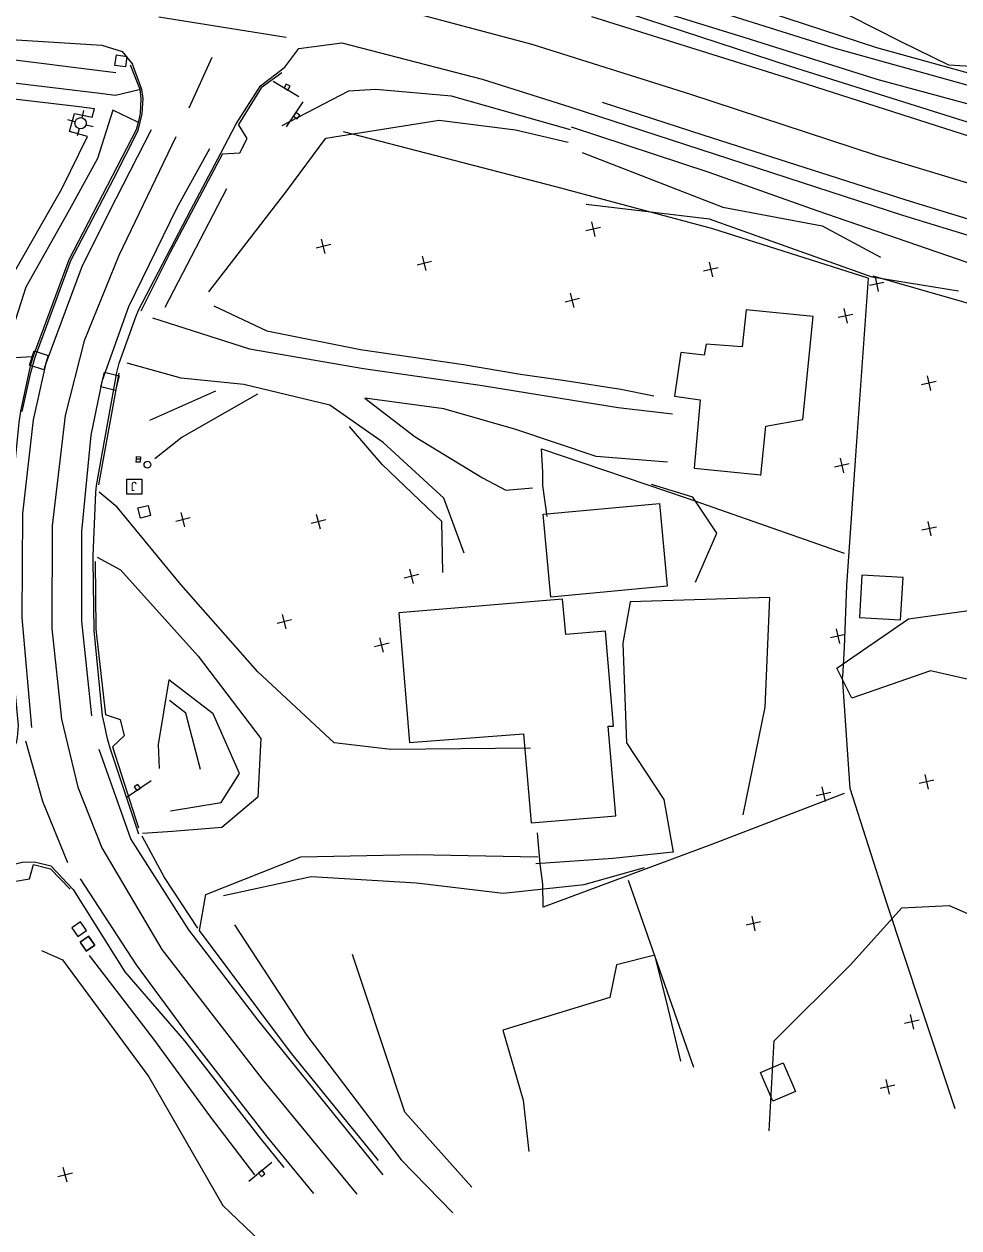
# Model space of a CAD drawing. Extents: x 4711259 to 4716401, y 890074 to 892728.
# Drawn here: x 4714778.1 to 4715089.6, y 890917.4 to 891318.6 of the extents above; entities that cross this region are included whole.
import ezdxf

# ---------------------------------------------------------------- set-up
doc = ezdxf.new("R2010")
doc.units = 0
for name, color, linetype in [('E_HY_STORM_Inlet', 7, 'Continuous'), ('E_LDSC_PHOTOG_Treeline', 7, 'Continuous'), ('E_RDWY_PHOTOG_Eave', 7, 'Continuous'), ('E_RDWY_PHOTOG_Fence', 7, 'Continuous'), ('E_RDWY_ROAD_Bikeway', 7, 'Continuous'), ('E_RDWY_ROAD_Curb', 7, 'Continuous'), ('E_RDWY_ROAD_EdgeAsph', 7, 'Continuous'), ('E_RDWY_ROAD_EdgeGravel', 7, 'Continuous'), ('E_RDWY_ROAD_Mailbox', 7, 'Continuous'), ('E_RDWY_ROAD_Sidewalk', 7, 'Continuous'), ('E_RDWY_ROAD_Striping', 7, 'Continuous'), ('E_RDWY_ROAD_TBofCurb', 7, 'Continuous'), ('E_TERR_DTM_BrkLines', 7, 'Continuous'), ('E_TERR_DTM_RandomPt', 7, 'Continuous'), ('E_TRAF_SIGN_PrivateSign', 7, 'Continuous'), ('E_TRAF_SIGN_PublicSign', 7, 'Continuous'), ('E_UTIL_COMM_General', 7, 'Continuous'), ('E_UTIL_ELEC_GENERAL', 7, 'Continuous'), ('E_UTIL_MISC_General', 7, 'Continuous'), ('E_UTIL_WTR_General', 7, 'Continuous')]:
    doc.layers.add(name, color=color, linetype=linetype)

msp = doc.modelspace()

# ---------------------------------------------------------------- linework, layer by layer
at = {"layer": 'E_HY_STORM_Inlet'}
for p, q in [((4714783.08, 891206.57), (4714783.08, 891206.57)), ((4714806.74, 891199.57), (4714806.74, 891199.57))]:
    msp.add_line(p, q, dxfattribs=at)
for points in [[(4714784.71, 891203.44), (4714779.95, 891204.94), (4714781.46, 891209.71), (4714786.22, 891208.2)], [(4714804.92, 891202.6), (4714809.77, 891201.38), (4714808.55, 891196.53), (4714803.7, 891197.75)]]:
    msp.add_lwpolyline(points, close=True, dxfattribs=at)
at = {"layer": 'E_LDSC_PHOTOG_Treeline'}
msp.add_lwpolyline([(4715107.9, 891096.71), (4715080.13, 891103.04), (4715053.95, 891093.97), (4715048.94, 891104), (4715072.76, 891120.43), (4715099.29, 891124.02), (4715112.14, 891115.47), (4715111.67, 891101.74)], dxfattribs=at)
at = {"layer": 'E_RDWY_PHOTOG_Eave'}
for points in [[(4715023.61, 891168.22), (4715025.23, 891184.62), (4715037.57, 891186.84), (4715040.98, 891221.12), (4715018.75, 891223.4), (4715017.35, 891211.08), (4715005.34, 891211.95), (4715004.68, 891208.27), (4714996.95, 891209.14), (4714994.86, 891194.66), (4715003.4, 891193.37), (4715001.35, 891170.57), (4715023.59, 891168.44)], [(4714906.49, 891079.18), (4714944.48, 891082.13), (4714947.08, 891052.41), (4714975.32, 891054.7), (4714972.73, 891084.6), (4714974.53, 891084.66), (4714971.82, 891116.26), (4714958.66, 891115.16), (4714957.47, 891126.94), (4714903.03, 891122.43), (4714906.5, 891079.08)]]:
    msp.add_lwpolyline(points, dxfattribs=at)
for points in [[(4714992.4, 891131.25), (4714953.62, 891127.68), (4714951.08, 891155.33), (4714989.85, 891158.9)], [(4715070.98, 891134.17), (4715057.25, 891134.96), (4715056.44, 891120.87), (4715070.17, 891120.08)], [(4715031.05, 890972.41), (4715035.15, 890962.91), (4715027.65, 890959.67), (4715023.54, 890969.17)]]:
    msp.add_lwpolyline(points, close=True, dxfattribs=at)
at = {"layer": 'E_RDWY_PHOTOG_Fence'}
for points in [[(4714955.27, 891264.38), (4714884.56, 891282.73)], [(4715059.4, 891233.98), (4715007.66, 891250.39), (4714955.27, 891264.38)], [(4715059.4, 891233.98), (4715055.24, 891176.4), (4715052.19, 891131.51), (4715051.31, 891110.84), (4715050.8, 891101.12)], [(4715186.39, 891197.91), (4715122.24, 891217.01), (4715061.03, 891234.6)], [(4714952.41, 891154.5), (4714950.96, 891164.8), (4714950.92, 891169.25), (4714950.57, 891177.09), (4714999.06, 891160.57), (4715051.34, 891142.26)], [(4715088.29, 890957.1), (4715077.12, 890990.71), (4715065.62, 891025.64), (4715053.37, 891063.81), (4715050.8, 891101.12)], [(4715051.31, 891062.18), (4715007.5, 891045.35), (4714951.11, 891024.27), (4714950.93, 891031.93), (4714950.11, 891038.8), (4714949.19, 891049.09)], [(4714979.38, 891033.35), (4715001.14, 890970.95)]]:
    msp.add_lwpolyline(points, dxfattribs=at)
at = {"layer": 'E_RDWY_ROAD_Bikeway'}
msp.add_lwpolyline([(4714960.53, 891338.2), (4714992.07, 891328.41), (4715047.87, 891310.67), (4715104.55, 891294.88), (4715161.82, 891279.58), (4715217.87, 891264.44), (4715268.34, 891251.28), (4715285.12, 891247.96), (4715289.15, 891255.65), (4715287.17, 891288.16), (4715277.94, 891331.31), (4715273.98, 891372.25)], dxfattribs=at)
at = {"layer": 'E_RDWY_ROAD_Curb'}
for points in [[(4714777.56, 891189.52), (4714780.34, 891202.47), (4714781.84, 891207.67), (4714793.67, 891239.87), (4714808, 891267.2), (4714816.14, 891283.15), (4714817.46, 891288.67), (4714817.8, 891293.79), (4714817.39, 891296.78), (4714814.29, 891305.29)], [(4714794.5, 891030.18), (4714787.19, 891037.94), (4714781.47, 891039.34), (4714777.5, 891039.18), (4714773.52, 891038.19), (4714769.87, 891037.1), (4714745.06, 891031.26), (4714715.63, 891028.71), (4714712.38, 891028.49), (4714697.92, 891027.61), (4714694.04, 891027.64), (4714666.46, 891026.17), (4714621.96, 891023.85), (4714619.54, 891023.9), (4714581.88, 891021.84), (4714537.04, 891019.62), (4714477.81, 891016.45)]]:
    msp.add_lwpolyline(points, dxfattribs=at)
at = {"layer": 'E_RDWY_ROAD_EdgeAsph'}
for points in [[(4715274.37, 891239.3), (4715279.91, 891242.26), (4715243.55, 891251.46), (4715202.85, 891263.05), (4715152.49, 891276.57), (4715108.79, 891287.62), (4715062.32, 891300.11), (4715019.77, 891313.64), (4714960.1, 891332.16)], [(4715104.58, 891282.25), (4715091.02, 891286.36), (4715033.48, 891304.49), (4714973.76, 891324.04), (4714960.29, 891328.61)], [(4714412.07, 891317.13), (4714421.12, 891318.22), (4714480.4, 891321.25), (4714536.91, 891324.63), (4714588.2, 891323.89), (4714641.59, 891321.38), (4714698.61, 891318.18), (4714754.2, 891314.67), (4714804.09, 891311.59), (4714810.85, 891309.49), (4714814.29, 891305.29)], [(4714865.02, 891304.31), (4714869.63, 891310.48), (4714883.99, 891312.35), (4714930.79, 891300.25), (4714959.91, 891291.07)], [(4714816.41, 891048.61), (4714806.85, 891077.27), (4714805.98, 891080.42), (4714804.92, 891085.14), (4714804.29, 891088.1), (4714801.49, 891116.55), (4714801.14, 891139.96), (4714801.17, 891141.55), (4714802.01, 891162.53), (4714802.27, 891164.88), (4714809.05, 891202.48), (4714809.84, 891205.61), (4714815.37, 891221.06), (4714816.31, 891223.24), (4714833.7, 891256.67), (4714843.66, 891275.57), (4714845.08, 891278.21), (4714847.52, 891282.87), (4714848.84, 891285.37), (4714856.94, 891298.05), (4714865.02, 891304.31)], [(4714959.91, 891291.07), (4715070.78, 891254.96), (4715096.24, 891247.13)], [(4714946.85, 891077.32), (4714900.38, 891076.82), (4714881.4, 891079.06), (4714856.02, 891102.71), (4714830.42, 891131.89), (4714809.11, 891157.66), (4714803.21, 891162.67)], [(4714802.51, 891140.94), (4714810.22, 891136.71), (4714836.16, 891107.98), (4714856.99, 891080.53), (4714856.07, 891061.02), (4714844.04, 891050.81), (4714827.56, 891049.54), (4714817.64, 891048.85)], [(4714896.24, 890939.9), (4714866.93, 890975.97), (4714836.57, 891016.5), (4714838.65, 891028.5), (4714870.33, 891041.1), (4714908.8, 891041.84), (4714949.25, 891041.14)], [(4714794.5, 891030.18), (4714811.75, 891002.79), (4714831.64, 890979.81), (4714856.81, 890947.31), (4714864.71, 890937.51)]]:
    msp.add_lwpolyline(points, dxfattribs=at)
at = {"layer": 'E_RDWY_ROAD_EdgeGravel'}
for points in [[(4715129.83, 891296.82), (4715131.22, 891300.37), (4715148.01, 891299.58), (4715169.77, 891296.66), (4715178.93, 891319.61), (4715159.28, 891322.41), (4715145.29, 891327.38), (4715136.27, 891339.29), (4715135.98, 891355.43), (4715142.7, 891381.21), (4715152.35, 891398.28), (4715174.07, 891425.28), (4715152.41, 891442.38), (4715131.25, 891448.73), (4715127.61, 891412.55), (4715124.8, 891383.92), (4715121.22, 891343.23), (4715118.2, 891317.27), (4715115.53, 891303.61), (4715110.39, 891299.56), (4715096.75, 891301.17), (4715062.25, 891310.71), (4715026.27, 891322.49), (4714993.7, 891330.91)], [(4714960.2, 891283.42), (4714920.51, 891294.62), (4714895.34, 891296.84), (4714886.25, 891296.23), (4714864.06, 891284.69)], [(4714960.4, 891284.34), (4715006.25, 891269.25), (4715042.29, 891256.46), (4715092.22, 891239.33), (4715128.79, 891228.29), (4715176.04, 891217.77), (4715229.02, 891205.03), (4715261.96, 891196.75), (4715272.04, 891183.8), (4715270.46, 891162.32), (4715267.8, 891132.71), (4715260.98, 891133.28)], [(4714845.57, 891263.7), (4714825.01, 891224.2)], [(4714820.98, 891220.75), (4714853.28, 891210.4), (4714891.25, 891203.84), (4714930.07, 891198.3), (4714976.11, 891190.86)], [(4714924.76, 891142.33), (4714917.96, 891160.57), (4714897.78, 891179.23), (4714880.03, 891191.59), (4714851.39, 891198.51), (4714830.49, 891200.67), (4714812.54, 891205.66)], [(4714992.46, 891172.66), (4714968.75, 891174.53), (4714942, 891183.48), (4714918, 891190.36), (4714891.72, 891193.98), (4714908.45, 891181.04), (4714930.91, 891167.4), (4714938.66, 891163.33), (4714947.5, 891164.06)], [(4714976.11, 891190.86), (4714994.19, 891188.73)], [(4714799.87, 891008.25), (4714821.3, 890980.32), (4714839.9, 890954.82), (4714854.95, 890935.06)], [(4714996.99, 890972.94), (4714992.22, 890993.02), (4714988.3, 891008.32), (4714975.54, 891005.12), (4714973.31, 890994.18), (4714937.59, 890983.32), (4714944.45, 890960.03), (4714946.31, 890942.91)]]:
    msp.add_lwpolyline(points, dxfattribs=at)
at = {"layer": 'E_RDWY_ROAD_Mailbox'}
for points in [[(4714798.97, 891016.57), (4714796.96, 891019.44), (4714794.09, 891017.43), (4714796.1, 891014.56)], [(4714801.67, 891011.77), (4714799.67, 891014.64), (4714796.8, 891012.63), (4714798.81, 891009.76)], [(4714801.67, 891011.66), (4714799.66, 891014.53), (4714796.8, 891012.52), (4714798.8, 891009.66)]]:
    msp.add_lwpolyline(points, close=True, dxfattribs=at)
at = {"layer": 'E_RDWY_ROAD_Sidewalk'}
for points in [[(4714816.5, 891296.69), (4714808.62, 891294.81), (4714802.45, 891295.59), (4714761.76, 891300.47)], [(4714759.61, 891295.53), (4714796.48, 891291.21), (4714801.58, 891290.53)], [(4714740.39, 891075.71), (4714762.07, 891076.89), (4714757.78, 891108.32), (4714757.55, 891143.53), (4714759.3, 891173.97), (4714761.75, 891192.58), (4714765.2, 891208.47), (4714758.18, 891210.11), (4714759.62, 891215.93), (4714767, 891214.2), (4714773.27, 891233.21), (4714790.74, 891263.77), (4714799.25, 891281.17), (4714793.25, 891282.77), (4714794.89, 891288.77), (4714800.82, 891287.57), (4714801.58, 891290.53)], [(4714816.03, 891285.88), (4714807.71, 891289.98), (4714802.61, 891273.83), (4714793.12, 891256.66), (4714778.72, 891230.97), (4714771.15, 891207.3), (4714780.69, 891207.86)], [(4714844.28, 891275.36), (4714850.06, 891275.66), (4714852.47, 891280.44), (4714849.57, 891285.19)], [(4714807.63, 891077.79), (4714811.61, 891081.53), (4714810.25, 891086.71), (4714805.32, 891088.38)], [(4714770.4, 891036.35), (4714774.68, 891032.83), (4714779.92, 891033.78), (4714781.25, 891038.5)]]:
    msp.add_lwpolyline(points, dxfattribs=at)
at = {"layer": 'E_RDWY_ROAD_Striping'}
for points in [[(4714888.76, 891327.56), (4714947.33, 891311.92)], [(4714967.14, 891321.14), (4715033.15, 891300.46), (4715090.68, 891282.05), (4715148, 891263.73), (4715202.12, 891249.54), (4715266.29, 891235.81)], [(4714947.33, 891311.92), (4715000.18, 891295.25), (4715061.97, 891274.93), (4715122.16, 891256.75), (4715178.28, 891241.22), (4715237.11, 891227.09), (4715270.84, 891220.22)], [(4714840.68, 891307.44), (4714833.04, 891290.62)], [(4715267.2, 891208.86), (4715234.23, 891215.79), (4715180.63, 891228.62), (4715123.12, 891244.3), (4715072.01, 891259.89), (4715004.43, 891281.64), (4714970.84, 891292.52)], [(4714780.77, 891084.16), (4714777.51, 891120.9), (4714777.75, 891155.5), (4714781.25, 891186.73), (4714785.5, 891205.56), (4714797.57, 891238.22), (4714808.77, 891260.52), (4714820.56, 891283.5)], [(4714828.68, 891281.1), (4714809.68, 891241.52), (4714798.18, 891213.11), (4714791.85, 891188.12), (4714787.48, 891151.35), (4714787.39, 891117.14), (4714790.61, 891086.99)], [(4714800.71, 891088.04), (4714797.34, 891119.61), (4714797.35, 891149.52), (4714800.49, 891181.6), (4714804.23, 891199.98), (4714813.01, 891224.55), (4714829.19, 891257.52), (4714840.04, 891277.19)], [(4714897.81, 890935.1), (4714856.04, 890986.77), (4714832.98, 891016.71), (4714813.74, 891047.11), (4714803.19, 891076.89)], [(4714804.01, 891044.05), (4714824.07, 891010.23), (4714857.48, 890967.03), (4714889.02, 890928.63)], [(4714874.69, 890928.88), (4714859.2, 890947.65), (4714832.98, 890981.42), (4714815.65, 891005.04), (4714796.93, 891033.8)]]:
    msp.add_lwpolyline(points, dxfattribs=at)
at = {"layer": 'E_RDWY_ROAD_TBofCurb'}
for points in [[(4714813.48, 891304.99), (4714816.67, 891296.91), (4714817.06, 891293.87), (4714816.78, 891288.8), (4714816.16, 891285.86), (4714815.48, 891283.33), (4714793.06, 891240.09), (4714781.17, 891207.95), (4714780.22, 891204.65), (4714776.92, 891189.64), (4714776.38, 891185.87), (4714773.42, 891155.74), (4714772.86, 891120.07), (4714776.18, 891084.87), (4714775.88, 891080.89), (4714775.48, 891079.03), (4714774.32, 891076.59), (4714769.02, 891071.22), (4714768.31, 891070.73), (4714764.77, 891068.82), (4714762.1, 891067.96)], [(4714864.03, 891302.4), (4714857.12, 891297.34), (4714849.57, 891285.19)], [(4714844.28, 891275.36), (4714826.87, 891242.7), (4714817.08, 891223)], [(4714809.67, 891202.23), (4714802.99, 891165.02)], [(4714801.85, 891139.47), (4714802.1, 891116.97), (4714805.32, 891088.38)], [(4714807.63, 891077.79), (4714816.31, 891050.76)], [(4714781.25, 891038.5), (4714786.94, 891037.11), (4714793.53, 891030.29)]]:
    msp.add_lwpolyline(points, dxfattribs=at)
at = {"layer": 'E_TERR_DTM_BrkLines'}
for points in [[(4715028.38, 891334.19), (4715070.04, 891312.89), (4715086.17, 891305.02), (4715103.25, 891304.05), (4715110.22, 891308.84), (4715118.68, 891335.69)], [(4714822.99, 891321.09), (4714865.48, 891314.24)], [(4714808.75, 891302.39), (4714767.9, 891307.46), (4714722.36, 891307.78), (4714714.06, 891307.54)], [(4714839.73, 891229.44), (4714865.66, 891263.03), (4714878.71, 891280.59), (4714916.43, 891286.57), (4714941.83, 891283.38), (4714959.42, 891279.22)], [(4714964.08, 891275.82), (4715010.94, 891257.66), (4715044.07, 891251.33), (4715063.52, 891240.94)], [(4715089.5, 891229.64), (4715060.7, 891234.33), (4715006.53, 891253.64), (4714965.42, 891258.52)], [(4714841.39, 891224.69), (4714859.01, 891216.42), (4714890.24, 891210.13), (4714924.58, 891205.19), (4714943.49, 891201.96), (4714958.39, 891199.79)], [(4714958.39, 891199.79), (4714977.01, 891196.91), (4714988, 891194.7)], [(4714841.94, 891196.3), (4714819.93, 891186.49)], [(4714855.89, 891195.29), (4714830.79, 891180.93), (4714821.66, 891173.7)], [(4714917.63, 891135.89), (4714917.36, 891152.83), (4714897.41, 891171.88), (4714886.53, 891184.54)], [(4715001.88, 891132.6), (4715008.9, 891148.95), (4715000.96, 891161), (4714987.18, 891165.17)], [(4715017.76, 891055.03), (4715024.99, 891090.99), (4715026.65, 891127.56), (4714980.02, 891126.03), (4714977.59, 891112.35), (4714978.86, 891079.11), (4714991.23, 891060.17), (4714994.44, 891042.64), (4714974.33, 891040.51), (4714948.66, 891038.72)], [(4714826.91, 891056.39), (4714843.77, 891059.2), (4714849.87, 891068.86), (4714841.15, 891088.7), (4714826.34, 891100.12), (4714822.79, 891078.56), (4714823.11, 891070.52)], [(4714836.92, 891070.16), (4714832.01, 891089), (4714826.58, 891093.2)], [(4714790.61, 891086.99), (4714796.05, 891064.33), (4714804.01, 891044.05)], [(4714778.59, 891079.73), (4714784.3, 891059.64), (4714792.58, 891039.19)], [(4714836.01, 891017.36), (4714824.95, 891034.23), (4714817.52, 891047.97)], [(4714844.57, 891028.22), (4714873.76, 891034.5), (4714908.86, 891032.44), (4714937.78, 891029.01), (4714964.71, 891031.91), (4714984.82, 891037.54)], [(4715026.42, 890949.72), (4715028.04, 890979.74), (4715053.31, 891005.02), (4715070.53, 891024.1), (4715086.38, 891024.84), (4715113.09, 891013.17), (4715126.01, 890996.89), (4715143.13, 890970.55), (4715149.96, 890957.06)], [(4714848.22, 891018.4), (4714872.31, 890981.54), (4714903.74, 890940.05), (4714921.04, 890922.39)], [(4714783.95, 891009.9), (4714790.89, 891006.8), (4714819.75, 890967.8), (4714844.39, 890924.9), (4714883.83, 890887.19), (4714907.11, 890866.26)], [(4714927.31, 890930.94), (4714904.95, 890955.98), (4714890.95, 890998.24), (4714887.58, 891008.53)]]:
    msp.add_lwpolyline(points, dxfattribs=at)
at = {"layer": 'E_TERR_DTM_RandomPt'}
for p, q in [((4714967.16, 891252.71), (4714968.25, 891247.83)), ((4714970.14, 891250.82), (4714965.26, 891249.73)), ((4714880.3, 891245.18), (4714875.46, 891243.93)), ((4714878.5, 891242.13), (4714877.25, 891246.97)), ((4714912.13, 891236.47), (4714910.88, 891241.31)), ((4714913.92, 891239.51), (4714909.08, 891238.26)), ((4715009.37, 891237.38), (4715004.49, 891236.29)), ((4715006.38, 891239.28), (4715007.47, 891234.4)), ((4715064.63, 891232.54), (4715059.75, 891231.45)), ((4715061.64, 891234.43), (4715062.73, 891229.55)), ((4714961.44, 891224.13), (4714960.19, 891228.97)), ((4714963.24, 891227.17), (4714958.4, 891225.92)), ((4715054.25, 891221.88), (4715049.37, 891220.79)), ((4715051.27, 891223.78), (4715052.36, 891218.9)), ((4715079.01, 891201.36), (4715080.1, 891196.48)), ((4715082, 891199.46), (4715077.12, 891198.37)), ((4715050.06, 891173.94), (4715051.15, 891169.06)), ((4715053.05, 891172.04), (4715048.17, 891170.95)), ((4714833.53, 891154.09), (4714828.69, 891152.84)), ((4714831.73, 891151.04), (4714830.48, 891155.88)), ((4714878.67, 891153.38), (4714873.83, 891152.13)), ((4714876.87, 891150.33), (4714875.62, 891155.17)), ((4715079.18, 891152.9), (4715080.27, 891148.02)), ((4715082.17, 891151.01), (4715077.29, 891149.92)), ((4714907.87, 891132.13), (4714906.62, 891136.97)), ((4714909.66, 891135.18), (4714904.82, 891133.93)), ((4714865.46, 891117.04), (4714864.21, 891121.88)), ((4714867.25, 891120.09), (4714862.41, 891118.83)), ((4715048.7, 891117.07), (4715049.79, 891112.19)), ((4714899.72, 891112.32), (4714894.88, 891111.07)), ((4714897.92, 891109.27), (4714896.67, 891114.11)), ((4715051.68, 891115.17), (4715046.8, 891114.08)), ((4715078.29, 891068.48), (4715079.38, 891063.6)), ((4715043.94, 891064.41), (4715045.03, 891059.53)), ((4715081.27, 891066.59), (4715076.39, 891065.5)), ((4715046.92, 891062.52), (4715042.04, 891061.43)), ((4715020.56, 891021.35), (4715021.65, 891016.47)), ((4715023.54, 891019.45), (4715018.66, 891018.36)), ((4715073.4, 890988.55), (4715074.49, 890983.67)), ((4715076.38, 890986.66), (4715071.5, 890985.57)), ((4715068.2, 890965.02), (4715063.32, 890963.93)), ((4715065.22, 890966.92), (4715066.31, 890962.04)), ((4714794.26, 890935.71), (4714789.42, 890934.46)), ((4714792.46, 890932.67), (4714791.21, 890937.51))]:
    msp.add_line(p, q, dxfattribs=at)
at = {"layer": 'E_TRAF_SIGN_PrivateSign'}
for p, q in [((4714865.52, 891284.35), (4714871.08, 891292.66)), ((4714868.92, 891288.09), (4714868.92, 891288.09))]:
    msp.add_line(p, q, dxfattribs=at)
msp.add_lwpolyline([(4714867.88, 891287.88), (4714869.13, 891287.05), (4714869.96, 891288.29), (4714868.72, 891289.13)], close=True, dxfattribs=at)
at = {"layer": 'E_TRAF_SIGN_PublicSign'}
for p, q in [((4714869.68, 891294.42), (4714861.09, 891299.54)), ((4714865.77, 891297.63), (4714865.77, 891297.63)), ((4714820.45, 891066.36), (4714812.15, 891060.79)), ((4714815.88, 891064.2), (4714815.88, 891064.2)), ((4714853.01, 890932.97), (4714860.73, 890939.32)), ((4714857.35, 890935.57), (4714857.35, 890935.57))]:
    msp.add_line(p, q, dxfattribs=at)
for points in [[(4714866.03, 891296.6), (4714866.8, 891297.89), (4714865.51, 891298.65), (4714864.74, 891297.37)], [(4714816.93, 891063.99), (4714816.09, 891065.24), (4714814.84, 891064.4), (4714815.68, 891063.16)], [(4714856.29, 890935.67), (4714857.24, 890934.51), (4714858.4, 890935.46), (4714857.45, 890936.62)]]:
    msp.add_lwpolyline(points, close=True, dxfattribs=at)
at = {"layer": 'E_UTIL_COMM_General'}
for points in [[(4714808.94, 891308.33), (4714812.4, 891307.82), (4714811.89, 891304.36), (4714808.42, 891304.87)], [(4714816.9, 891154), (4714816.07, 891157.4), (4714819.47, 891158.23), (4714820.3, 891154.83)]]:
    msp.add_lwpolyline(points, close=True, dxfattribs=at)
at = {"layer": 'E_UTIL_ELEC_GENERAL'}
msp.add_lwpolyline([(4714812.38, 891167.01), (4714817.38, 891166.97), (4714817.33, 891161.97), (4714812.33, 891162.01)], close=True, dxfattribs=at)
at = {"layer": 'E_UTIL_MISC_General'}
for points in [[(4714816.78, 891172.57), (4714815.49, 891172.64), (4714815.55, 891173.71), (4714816.84, 891173.64)], [(4714815.55, 891173.71), (4714815.58, 891174.47), (4714816.92, 891174.4), (4714816.88, 891173.64)]]:
    msp.add_lwpolyline(points, close=True, dxfattribs=at)
msp.add_circle((4714819.23, 891171.78), 1.12, dxfattribs=at)
at = {"layer": 'E_UTIL_WTR_General'}
for p, q in [((4714797.45, 891287.38), (4714798.09, 891289.8)), ((4714795.16, 891286.05), (4714792.74, 891286.69)), ((4714798.78, 891285.09), (4714801.2, 891284.44)), ((4714796.49, 891283.76), (4714795.85, 891281.34))]:
    msp.add_line(p, q, dxfattribs=at)
msp.add_circle((4714796.97, 891285.57), 1.87, dxfattribs=at)

# ---------------------------------------------------------------- texts
at = {"layer": 'E_UTIL_ELEC_GENERAL'}
msp.add_text('J', height=3, rotation=179.4836, dxfattribs=at).set_placement((4714815.72, 891166.05))

doc.saveas('drawing.dxf')
